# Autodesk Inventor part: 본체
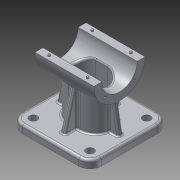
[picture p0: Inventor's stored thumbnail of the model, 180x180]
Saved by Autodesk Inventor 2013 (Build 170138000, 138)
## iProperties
Created: 2015-12
Part Number: 본체
Material: 알루미늄 6061
Document SubType Name: Modeling
Designer: mduedu
Density: 2.71 g/cm^3
Author: mduedu
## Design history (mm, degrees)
sketch "스케치1"
  geometry: L1 (-50, -50)-(50, -50); L2 (50, -50)-(50, 50); L3 (50, 50)-(-50, 50); L4 (-50, 50)-(-50, -50); L5 (-50, -50)-(50, 50); L6 (50, -50)-(-50, 50); 2 further points
  constraints: 12 end point, 2 midpoint, 2 parallel, 1 coincident, 1 horizontal, 1 perpendicular
  dimensions: "d154" = 100 distance of L2.end L3.end; "d155" = 100 distance of L3.end L1.start
extrude "돌출1" new body sketch "스케치1" distance "d3" = 10; taper "d4" = 0 deg
sketch "스케치2"
  geometry: C1 r 32.5 at (80, 0); 1 further point
  constraints: 1 centre point, 1 horizontal alignment
  dimensions: "d5" = 65 diameter of C1; "d125" = 80 distance of C1.centre point (0, 0)
extrude "돌출2" join sketch "스케치2" stored distance "d7" = 75; taper "d8" = 0 deg
sketch "스케치3"
  geometry: L1 (-27.5, -20)-(27.5, -20); L2 (27.5, -20)-(27.5, 20); L3 (27.5, 20)-(-27.5, 20); L4 (-27.5, 20)-(-27.5, -20); L5 (-27.5, -20)-(27.5, 20); L6 (27.5, -20)-(-27.5, 20); 1 further point
  constraints: 12 end point, 2 midpoint, 2 parallel, 1 horizontal, 1 perpendicular
  dimensions: "d9" = 55 distance of L2.end L3.end; "d11" = 40 distance of L1.end L2.end
extrude "돌출3" new body sketch "스케치3" stored distance "d12" = 75; taper "d13" = 0 deg
fillet "모깎기1"
fillet "모깎기2"
feature "결합1"
  node "솔리드2"
sketch "스케치4"
  geometry: L1 (-37.5, 47.5)-(37.5, 47.5) reference; L2 (32.5, 47.5)-(39.112, 10); L3 (37.5, 47.5)-(37.5, 112.5) reference; L4 (50, 10)-(-50, 10) reference; 1 further point
  constraints: 2 end point, 2 point on line
  dimensions: "d15" = 5 distance from line of L2.start L3; "d126" = 80 deg angle of L2 L1
feature "리브1" dims "d19" = 1, "d20" = 6, "d21" = 0, "d22" = 0, "d23" = 1, "d24" = 1
feature "리브2" dims "d25" = 1, "d26" = 6, "d27" = 0, "d28" = 0, "d29" = 1, "d30" = 1
fillet "모깎기4" dims "d31" = 2
fillet "모깎기5" dims "d32" = 2
fillet "모깎기6" dims "d33" = 2
fillet "모깎기7" dims "d41" = 14
hole "구멍2" diameter "d44" = 45; stored, may be unused: countersink angle "d48" = 90 deg, drill point angle "d50" = 118 deg; dims "d42" = 10, "d43" = 10, "d45" = 6, "d46" = 4, "d47" = 2, "d49" = 8
sketch "스케치7" dims "d52" = 26.5
  geometry: L1 (0, 0)-(32.5, 0); L2 (0, 0)-(22.981, 22.981); A1 r 32.5 centre (0, 0) between (32.5, 0) and (22.981, 22.981) reference; 3 further points
  constraints: 4 end point, 2 point on circle, 1 coincident, 1 horizontal, 1 point on line, 3 other
  dimensions: "d51" = 45 deg angle of L2 L1
hole "구멍3" sketch "스케치7" at (18.738, 18.738) diameter "d54" = 2.459; stored, may be unused: countersink angle "d58" = 90 deg, drill point angle "d60" = 118 deg; dims "d55" = 8, "d56" = 4, "d57" = 2, "d59" = 10
sketch "스케치9"
  geometry: L1 (-75, 82.5)-(75, 82.5); L2 (75, 82.5)-(75, 0); L3 (75, 0)-(-75, 0); L4 (-75, 0)-(-75, 82.5); C1 r 32.5 at (0, 0) reference; 2 further points
  constraints: 8 end point, 2 parallel, 1 coincident, 1 horizontal, 1 midpoint, 1 perpendicular
  dimensions: "d71" = 50 distance edge to line of C1 L1; "d116" = 150 distance between parallel lines of L2 L4
extrude "돌출5" cut sketch "스케치9" stored distance "d73" = 0; taper "d74" = 0 deg
node "작업 평면1"
sketch "스케치10"
  geometry: L1 (-7.5, 15)-(7.5, 15); L2 (-7.5, -15)-(7.5, -15); A1 r 20 centre (-7.5, 0) between (-7.5, 20) and (-26.977, 4.545) reference; A2 r 20 centre (7.5, 0) between (26.977, 4.545) and (7.5, 20) reference; A3 r 15 centre (-7.5, 0) between (-7.5, 15) and (-7.5, -15); A4 r 15 centre (7.5, 0) between (7.5, -15) and (7.5, 15); 1 further point
  constraints: 7 point on circle, 4 end point, 4 tangent, 3 point on line, 2 centre point, 2 coincident, 1 horizontal
  dimensions: "d77" = 5 radial gap between concentric circles of A3 A1
extrude "돌출6" cut sketch "스케치10" stored distance "d78" = 50; taper "d79" = 0 deg
fillet "모깎기10" dims "d80" = 3
sketch "스케치11"
  geometry: 2 further points
  constraints: 1 coincident
hole "구멍4" sketch "스케치11" at (0, 0) diameter "d81" = 12; stored, may be unused: countersink angle "d85" = 90 deg, drill point angle "d87" = 118 deg; dims "d82" = 8, "d83" = 40, "d84" = 10, "d86" = 10
sketch "스케치12"
  geometry: C1 r 10 at (0, 0); 1 further point
  constraints: 1 centre point, 1 coincident
  dimensions: "d88" = 20 diameter of C1
extrude "돌출7" cut sketch "스케치12" distance "d89" = 5; taper "d90" = 0 deg
chamfer "모따기1" distance "d91" = 1; stored, may be unused: second distance "d92" = 2, angle "d93" = 45 deg
fillet "모깎기11" dims "d94" = 0.5
fillet "모깎기12" dims "d115" = 0.3
sketch "스케치15"
  geometry: L1 (-75, 55)-(-75, 65) reference; L2 (0, 65)-(0, 55) reference; L3 (-75, 60)-(0, 60); C1 r 1.5 at (-62, 60); 1 further point
  constraints: 2 end point, 2 midpoint, 1 centre point, 1 point on line
  dimensions: "d117" = 3 diameter of C1; "d118" = 13 distance from line of C1.centre L1
extrude "돌출8" join sketch "스케치15" distance "d119" = 1.8; taper "d120" = 0 deg
chamfer "모따기2" distance "d121" = 0.5; stored, may be unused: second distance "d122" = 2, angle "d123" = 45 deg
sketch "스케치19"
  geometry: A1 r 14 centre (-36, -36) between (-50, -36) and (-36, -50) reference; A2 r 14 centre (-36, 36) between (-36, 50) and (-50, 36) reference; A3 r 14 centre (36, 36) between (50, 36) and (36, 50) reference; A4 r 14 centre (36, -36) between (36, -50) and (50, -36) reference; 5 further points
  constraints: 4 coincident
hole "구멍9" sketch "스케치19" at (-36, -36), (36, -36), (36, 36), (-36, 36) diameter "d156" = 10; stored, may be unused: countersink angle "d160" = 90 deg, drill point angle "d162" = 0 deg; dims "d157" = 6, "d158" = 4, "d159" = 2, "d161" = 8
node "솔리드1"
sketch "스케치5"
  geometry: L1 (10, 35)-(56.569, 22.522); L2 (10, 20)-(54.383, 20) reference; L3 (10, -50)-(10, 50) reference; A1 r 32.5 centre (80, 0) between (56.569, 22.522) and (54.383, 20) reference; 1 further point
  constraints: 2 end point, 1 point on circle, 1 point on line
  dimensions: "d128" = 15 distance of L1.start L2.start
mirror "대칭1"
mirror "대칭2"
pattern_circular "원형 패턴1" dims angle "d62" = 360 deg
mirror "대칭3"
mirror "대칭5"
mirror "대칭6"
